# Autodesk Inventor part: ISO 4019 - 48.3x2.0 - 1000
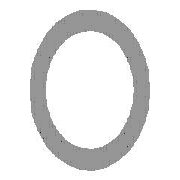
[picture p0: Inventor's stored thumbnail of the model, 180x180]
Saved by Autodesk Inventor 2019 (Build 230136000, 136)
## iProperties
IsCustomPart: 1
Created: 2018-01
Part Number: ISO 4019 - 48.3x2.0 - 1000
Material: Acier, doux
Description: Aciers de construction - Coupes creuses profilées formées à froid, soudées
Document SubType Name: Modeling
Standard: ISO
Designer: Fabian Perrée
Standard Revision: Second edition 2001-09-01
Standards Organization: ISO
Language: fr-FR
Size Designation: 48.3x2.0
Categories: <MemberInstance><Categories><Category DisplayName="Profilés" InternalName="089c4875-fa83-4c05-b084-43b9cc11f5ed" Mnemonic="GRDR"><CategoryParameter DisplayName=
Stock Number: 48.3x2.0
Density: 7.85 g/cm^3
Appearance: Semi-poli
Mass: 2169.32 g
Surface Area: 2784.02 cm^2
Volume: 276.347 cm^3
G_L: 1000,000 mm
G_W: 48,300 mm
G_H: 48,300 mm
+F65DF18C-8240-4B37-BE7E-B19A84124B65+DETAILDECOUPE1: Grugeage
+777B3F36-A96D-4E13-B6C7-D3E31DCB894B+DETAILDECOUPE2: Grugeage
_CCFamilyMember: 14
_CCFamilyDisplayName: ISO 4019 (Profils creux circulaires - Formés à froid) - Aciers de construction - Coupes creuses profilées formées à froid, soudées — ISO 4019 (Profils creux cir
_FrameMemberDoc: Frame Member File
_Version: 15.0.0
_GetPNFromCC: 1
Author: Fabian Perrée
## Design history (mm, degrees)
node "Plan de départ"
node "Plan de fin"
sketch "Esquisse"
  geometry: C1 r 22.15 at (0, 0); C2 r 24.15 at (0, 0); 2 further points
  constraints: 3 coincident, 2 centre point
  dimensions: "d0" = 48.3 diameter of C2 (= G_H); "d1" = 2 radial gap between concentric circles of C2 C1 (= G_T)
extrude "Corps" new body sketch "Esquisse" stored distance "d2" = 1000 (= G_L); taper "d3" = 0 deg
node "Driven Length"
  sketch "Sketch3"
    geometry: L1 (0, 0)-(10, 0) reference
    constraints: 2 end point, 1 horizontal
  workplane "Work Plane3"
  sketch "Sketch4"
    geometry: L1 (-2, 0)-(12, 0) reference; L2 (-2, 1000)-(12, 1000) reference
    dimensions: "d7" = 1000 distance between parallel lines of L1 L2 (derived)
body "Solid1"
feature "Sculpter1"
feature "Combiner1"
feature "Sculpter3"
feature "Combiner3"
body "Srf11"
body "Srf12"
node "Solide5"
body "Srf14"
body "Srf15"
node "Solide6"
feature "Surface1"
body "Srf10"
feature "Carreau délimité7" dims "d20" = 5, "d21" = 0
feature "Carreau délimité8" dims "d22" = 5, "d23" = 0
feature "Surface3"
body "Srf13"
feature "Carreau délimité9" dims "d24" = 5, "d25" = 0
feature "Carreau délimité10" dims "d26" = 5, "d27" = 0
other parameters: "G_H" = 48.3 [user parameter; used in 1 equation term], "G_T" = 2 [user parameter; used in 1 equation term], "G_L" = 1000 (= d7) [user parameter; used in 1 equation term], "G_OFFSET_START" = 0 [user parameter; used in 1 equation term], "G_OFFSET_END" = 0 [user parameter; used in 1 equation term], "d4" = 0 (computed from G_OFFSET_START), "d5" = 1000 (= G_OFFSET_END + B_L), "B_L" = 1000 [user parameter; used in 1 equation term], "d6" = 90 deg, "MAS" = 0.228 [user parameter]
